Omron CX-Programmer project NuevoProyecto (CX-Programmer 9.50)

# PLC NewPLC1: CP1L-E EM

## Program P5 (cyclic task 0)
Local symbols
A 100.00 BOOL
ACP 100.07 BOOL
AL1 101.00 BOOL
AL2 101.01 BOOL
B 100.01 BOOL
Etapa_0 10.00 BOOL
Etapa_1 10.01 BOOL
Etapa_2 10.02 BOOL
Etapa_3 10.03 BOOL
Etapa_4 10.04 BOOL
Etapa_5 10.05 BOOL
Etapa_6 10.06 BOOL
Etapa_7 10.07 BOOL
Etapa_8 10.08 BOOL
FC1 0.03 BOOL
FC2 0.04 BOOL
LC 100.06 BOOL
LR_1 100.02 BOOL
LR_2 100.03 BOOL
LV1 100.04 BOOL
LV2 100.05 BOOL
S_1 0.01 BOOL
S_2 0.02 BOOL
m 0.00 BOOL

### Section Sección1_Programa_principal
; Programa principal (Etapas 0 ... 8)

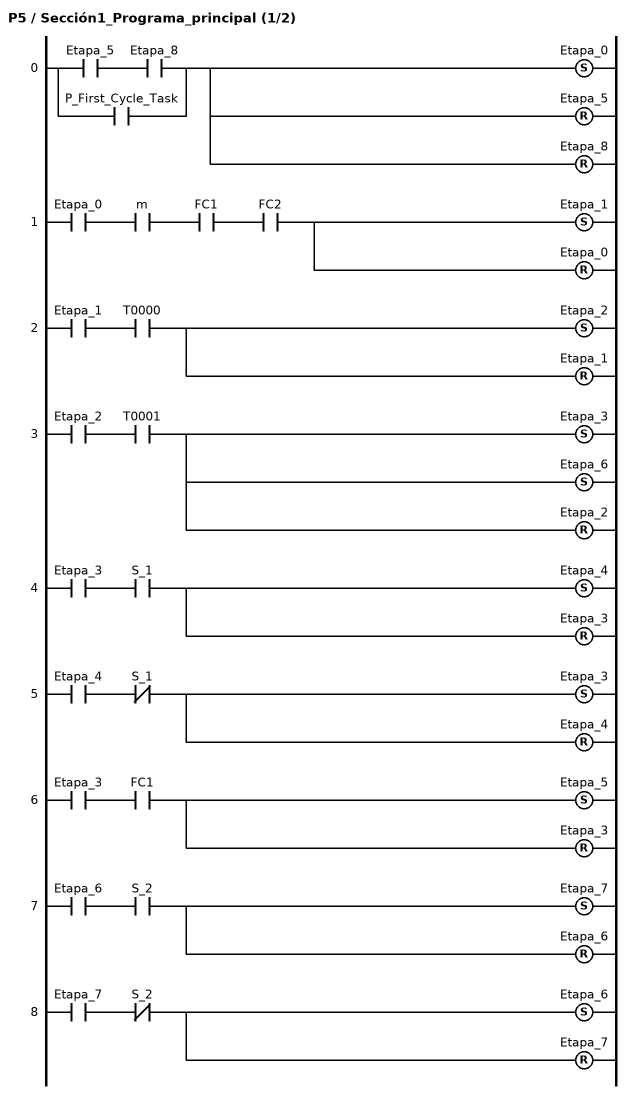
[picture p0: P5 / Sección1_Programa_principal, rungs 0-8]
; rung 0
LD Etapa_5
AND Etapa_8
OR P_First_Cycle_Task
SET Etapa_0
RSET Etapa_5
RSET Etapa_8
; rung 1
LD Etapa_0
AND m
AND FC1
AND FC2
SET Etapa_1
RSET Etapa_0
; rung 2
LD Etapa_1
AND T0000
SET Etapa_2
RSET Etapa_1
; rung 3
LD Etapa_2
AND T0001
SET Etapa_3
SET Etapa_6
RSET Etapa_2
; rung 4
LD Etapa_3
AND S_1
SET Etapa_4
RSET Etapa_3
; rung 5
LD Etapa_4
ANDNOT S_1
SET Etapa_3
RSET Etapa_4
; rung 6
LD Etapa_3
AND FC1
SET Etapa_5
RSET Etapa_3
; rung 7
LD Etapa_6
AND S_2
SET Etapa_7
RSET Etapa_6
; rung 8
LD Etapa_7
ANDNOT S_2
SET Etapa_6
RSET Etapa_7

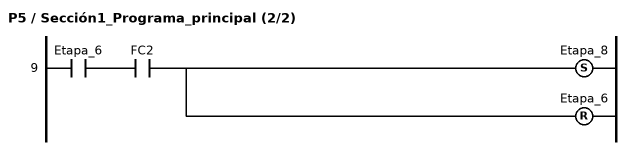
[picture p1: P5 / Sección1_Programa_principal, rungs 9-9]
; rung 9
LD Etapa_6
AND FC2
SET Etapa_8
RSET Etapa_6

### Section Sección2_Temporizadores

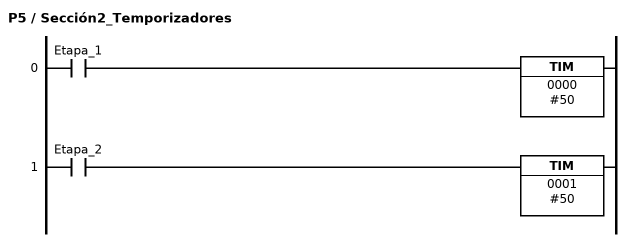
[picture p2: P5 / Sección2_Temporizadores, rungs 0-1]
; rung 0
LD Etapa_1
TIM 0000 #50
; rung 1
LD Etapa_2
TIM 0001 #50

### Section Sección3_Salidas

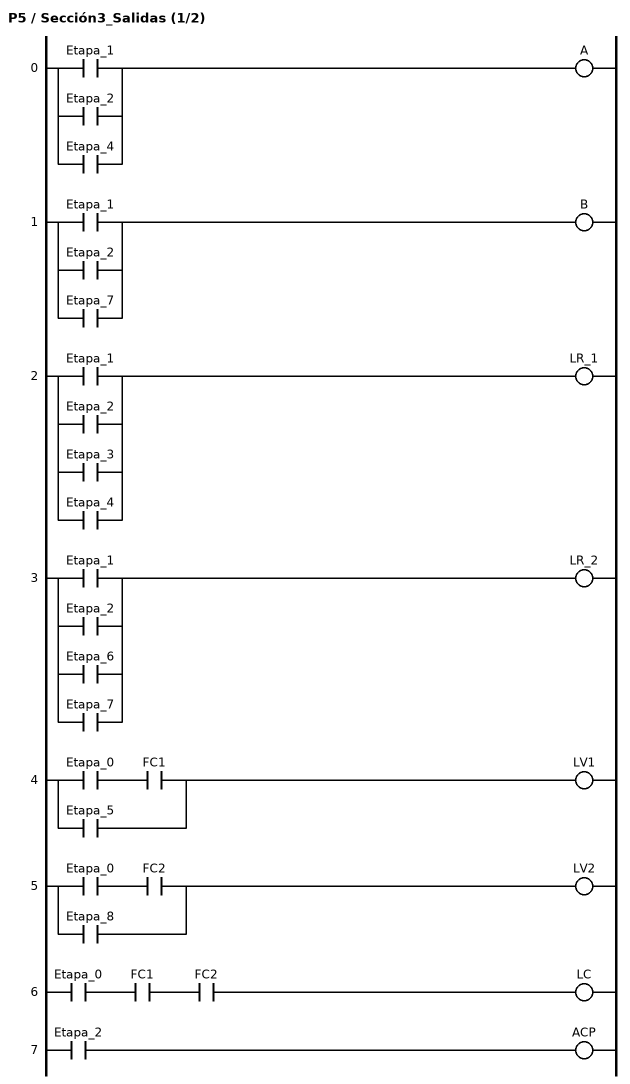
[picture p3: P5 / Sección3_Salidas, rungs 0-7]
; rung 0
LD Etapa_1
OR Etapa_2
OR Etapa_4
OUT A
; rung 1
LD Etapa_1
OR Etapa_2
OR Etapa_7
OUT B
; rung 2
LD Etapa_1
OR Etapa_2
OR Etapa_3
OR Etapa_4
OUT LR_1
; rung 3
LD Etapa_1
OR Etapa_2
OR Etapa_6
OR Etapa_7
OUT LR_2
; rung 4
LD Etapa_0
AND FC1
OR Etapa_5
OUT LV1
; rung 5
LD Etapa_0
AND FC2
OR Etapa_8
OUT LV2
; rung 6
LD Etapa_0
AND FC1
AND FC2
OUT LC
; rung 7
LD Etapa_2
OUT ACP

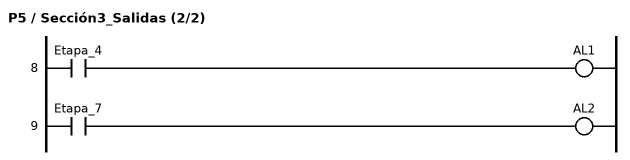
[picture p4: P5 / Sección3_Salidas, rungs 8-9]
; rung 8
LD Etapa_4
OUT AL1
; rung 9
LD Etapa_7
OUT AL2

### Section Sección4_END
; rung 0: Fin de programa
END(001)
